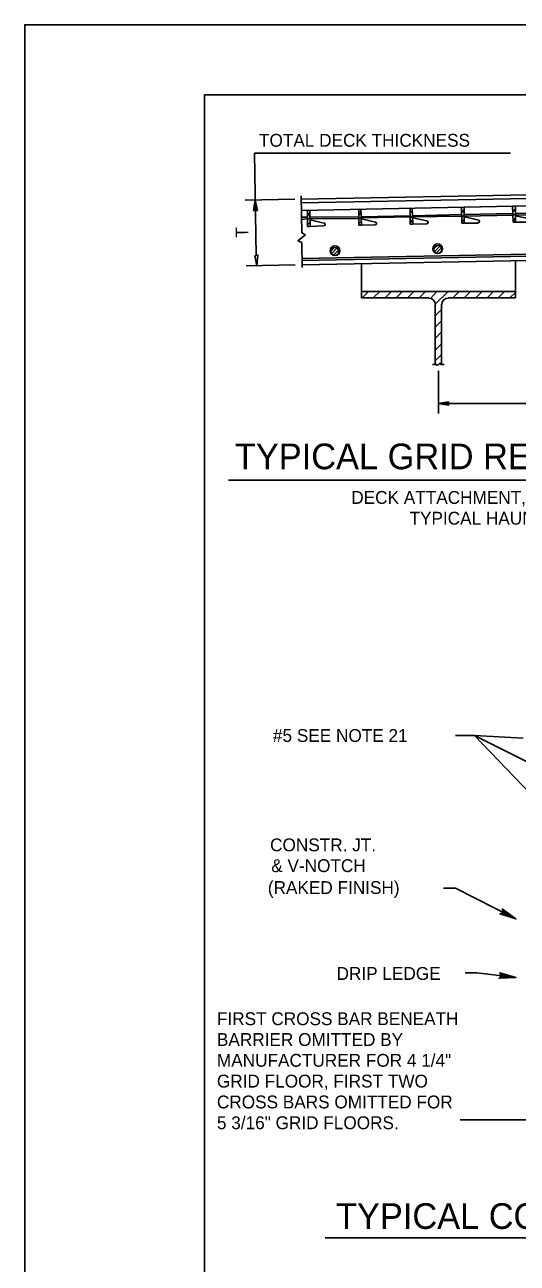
# Model space of a CAD drawing. Extents: x -24512 to -22484, y 4569 to 6351.
# Drawn here: x -24179.8 to -24064.8, y 6061.6 to 6351 of the extents above; entities that cross this region are included whole.
import ezdxf

# ---------------------------------------------------------------- set-up
doc = ezdxf.new("R2010")
doc.units = 0
for name, color, linetype in [('10', 7, 'Continuous'), ('11', 7, 'Continuous'), ('2', 7, 'Continuous'), ('4', 7, 'Continuous'), ('5', 7, 'Continuous'), ('6', 7, 'Continuous'), ('PLT-BNDY', 7, 'Continuous')]:
    doc.layers.add(name, color=color, linetype=linetype)

# ---------------------------------------------------------------- blocks, each defined once
blk = doc.blocks.new('JUQ006')
at = {"layer": '4'}
for p, q in [((10.418625, 11.48775), (10.630375, 11.699625)), ((10.457, 11.312375), (10.805875, 11.66125)), ((10.574625, 11.21625), (10.902, 11.5435)), ((10.82875, 11.256375), (10.86175, 11.2895))]:
    blk.add_line(p, q, dxfattribs=at)
blk = doc.blocks.new('JUQ005')
at = {"layer": '4'}
for p, q in [((12.764875, 6.492125), (12.825, 6.552375)), ((12.764875, 6.207), (12.916, 6.35825)), ((12.764875, 5.921875), (12.916, 6.073125)), ((12.764875, 5.63675), (12.916, 5.788))]:
    blk.add_line(p, q, dxfattribs=at)

msp = doc.modelspace()

# ---------------------------------------------------------------- linework, layer by layer
at = {"layer": '10'}
for p, q in [((-24066.39, 6321.05), (-24126.15, 6321.05)), ((-24125.71, 6297.2), (-24126.15, 6321.05)), ((-24116.73, 6310.29), (-24128.33, 6310.04)), ((-24116.6, 6294.95), (-24128.08, 6294.7)), ((-24083.19, 6270.14), (-24083.19, 6260.17)), ((-24083.19, 6262.53), (-23939.17, 6262.53)), ((-24074.73, 6184.92), (-24079.19, 6184.92)), ((-24062.64, 6178.84), (-24074.73, 6184.92)), ((-24063.38, 6184.3), (-24074.73, 6184.92)), ((-24061.72, 6171.26), (-24074.73, 6184.92)), ((-24079.24, 6149.28), (-24081.98, 6149.28)), ((-24065.08, 6142.05), (-24079.24, 6149.28)), ((-24074.23, 6129.43), (-24076.97, 6129.43)), ((-24065.08, 6128.37), (-24074.23, 6129.43)), ((-24048.21, 6095.14), (-24078.1, 6095.14))]:
    msp.add_line(p, q, dxfattribs=at)
for points in [[(-24126.33, 6307.67), (-24125.46, 6307.67), (-24125.96, 6310.04)], [(-24126.08, 6297.07), (-24125.33, 6297.2), (-24125.58, 6294.7)], [(-24080.82, 6262.91), (-24080.82, 6262.16), (-24083.19, 6262.53)]]:
    msp.add_lwpolyline(points, close=True, dxfattribs=at)
for points in [[(-24068.16, 6144.14), (-24068.16, 6143.84), (-24065.08, 6142.05), (-24068.16, 6144.14), (-24068.26, 6144.37), (-24065.08, 6142.05), (-24068.33, 6143.51), (-24068.56, 6143.33), (-24065.08, 6142.05), (-24068.82, 6143.26), (-24068.56, 6143.33)], [(-24068.7, 6129.26), (-24068.59, 6128.97), (-24065.08, 6128.37), (-24068.7, 6129.26), (-24068.87, 6129.44), (-24065.08, 6128.37), (-24068.63, 6128.6), (-24068.79, 6128.36), (-24065.08, 6128.37), (-24069.01, 6128.2), (-24068.79, 6128.36)]]:
    msp.add_lwpolyline(points, dxfattribs=at)
at = {"layer": '11'}
for p, q in [((-23876.11, 6244.57), (-24132.21, 6244.57)), ((-23923.43, 6067.54), (-24109.65, 6067.54))]:
    msp.add_line(p, q, dxfattribs=at)
at = {"layer": '2'}
for p, q in [((-24137.79, 5772.04), (-24137.79, 6334.63)), ((-24137.79, 6334.63), (-23353.75, 6334.63))]:
    msp.add_line(p, q, dxfattribs=at)
at = {"layer": '5'}
for p, q in [((-24115.23, 6310.29), (-23904.64, 6314.4)), ((-24115.23, 6309.42), (-23904.64, 6313.41)), ((-24115.23, 6307.67), (-23904.64, 6311.79)), ((-24115.23, 6311.04), (-24115.11, 6302.43)), ((-24113.74, 6307.67), (-24113.74, 6303.93)), ((-24113.24, 6307.67), (-24113.11, 6303.93)), ((-24101.77, 6307.92), (-24101.77, 6304.18)), ((-24101.27, 6307.92), (-24101.14, 6304.18)), ((-24089.8, 6308.17), (-24089.8, 6304.43)), ((-24089.3, 6308.17), (-24089.17, 6304.43)), ((-24077.83, 6308.42), (-24077.7, 6304.68)), ((-24077.2, 6308.42), (-24077.2, 6304.68)), ((-24065.86, 6308.67), (-24065.73, 6304.93)), ((-24065.23, 6308.67), (-24065.23, 6304.93)), ((-24115.23, 6306.05), (-24113.74, 6306.05)), ((-24115.23, 6305.55), (-24113.74, 6305.68)), ((-24113.24, 6306.05), (-24101.77, 6306.18)), ((-24113.24, 6305.68), (-24101.77, 6305.8)), ((-24113.24, 6305.43), (-24109.87, 6304.68)), ((-24101.14, 6306.18), (-24089.8, 6306.42)), ((-24101.14, 6305.93), (-24089.8, 6306.18)), ((-24101.14, 6305.68), (-24097.9, 6304.93)), ((-24089.8, 6304.43), (-24089.17, 6304.43)), ((-24089.17, 6306.42), (-24077.83, 6306.67)), ((-24089.17, 6306.18), (-24077.83, 6306.3)), ((-24089.17, 6305.93), (-24085.93, 6305.18)), ((-24089.17, 6304.43), (-24085.93, 6304.55)), ((-24077.7, 6304.68), (-24077.2, 6304.68)), ((-24077.2, 6306.67), (-24065.86, 6306.92)), ((-24077.2, 6306.3), (-24065.73, 6306.55)), ((-24077.2, 6306.18), (-24073.96, 6305.43)), ((-24077.2, 6304.68), (-24073.96, 6304.68)), ((-24065.73, 6304.93), (-24065.23, 6304.93)), ((-24065.23, 6306.92), (-24053.76, 6307.17)), ((-24065.23, 6306.55), (-24053.76, 6306.8)), ((-24065.23, 6306.42), (-24061.87, 6305.68)), ((-24065.23, 6304.93), (-24061.99, 6304.93)), ((-24115.98, 6300.56), (-24114.24, 6301.94)), ((-24115.11, 6302.43), (-24114.24, 6301.94)), ((-24113.74, 6303.93), (-24113.11, 6303.93)), ((-24113.11, 6303.93), (-24110, 6304.06)), ((-24101.77, 6304.18), (-24101.14, 6304.18)), ((-24101.14, 6304.18), (-24097.9, 6304.31)), ((-24115.98, 6300.56), (-24115.11, 6300.19)), ((-24115.11, 6296.45), (-23904.51, 6300.44)), ((-24115.11, 6300.19), (-24114.98, 6294.33)), ((-24115.11, 6295.95), (-23904.51, 6299.94)), ((-24114.98, 6294.95), (-23904.51, 6298.94)), ((-24065.23, 6288.72), (-24065.23, 6295.95)), ((-24101.14, 6288.72), (-24101.14, 6295.2)), ((-24101.14, 6288.72), (-24065.23, 6288.72)), ((-24101.14, 6288.72), (-24101.14, 6287.22)), ((-24101.14, 6287.22), (-24085.43, 6287.22)), ((-24080.94, 6287.22), (-24065.23, 6287.22)), ((-24065.23, 6288.72), (-24065.23, 6287.22)), ((-24083.94, 6285.73), (-24083.94, 6271.64)), ((-24082.44, 6285.73), (-24082.44, 6271.64)), ((-24084.56, 6271.64), (-24083.56, 6271.64)), ((-24083.56, 6271.64), (-24083.44, 6271.39)), ((-24083.44, 6271.39), (-24082.81, 6272.01)), ((-24082.81, 6272.01), (-24082.69, 6271.64)), ((-24082.69, 6271.64), (-24081.82, 6271.64)), ((-24080.82, 6262.53), (-24080.82, 6262.53))]:
    msp.add_line(p, q, dxfattribs=at)
for centre, radius in [((-24107.35, 6298.23), 1.13), ((-24107.35, 6298.04), 0.938), ((-24083.35, 6298.69), 1.13), ((-24083.35, 6298.5), 0.938)]:
    msp.add_circle(centre, radius, dxfattribs=at)
for centre, radius, start, end in [((-24109.99, 6304.42), 0.375, 271.0964, 77.9991), ((-24097.99, 6304.64), 0.375, 271.0964, 77.9991), ((-24085.99, 6304.87), 0.375, 271.0964, 77.9991), ((-24073.99, 6305.1), 0.375, 271.0964, 77.9991), ((-24085.41, 6285.65), 1.5, 0, 90), ((-24080.91, 6285.65), 1.5, 90, 180)]:
    msp.add_arc(centre, radius, start, end, dxfattribs=at)
at = {"layer": '6'}
for p, q in [((-24101.02, 6287.22), (-24099.52, 6288.72)), ((-24098.4, 6287.22), (-24096.9, 6288.72)), ((-24095.66, 6287.22), (-24094.16, 6288.72)), ((-24093.04, 6287.22), (-24091.54, 6288.72)), ((-24090.42, 6287.22), (-24088.92, 6288.72)), ((-24087.68, 6287.22), (-24086.18, 6288.72)), ((-24085.06, 6287.1), (-24083.56, 6288.72)), ((-24083.94, 6285.73), (-24080.94, 6288.72)), ((-24079.82, 6287.22), (-24078.33, 6288.72)), ((-24077.2, 6287.22), (-24075.71, 6288.72)), ((-24074.46, 6287.22), (-24072.96, 6288.72)), ((-24071.84, 6287.22), (-24070.35, 6288.72)), ((-24069.22, 6287.22), (-24067.73, 6288.72)), ((-24066.48, 6287.22), (-24065.23, 6288.47)), ((-24083.94, 6282.98), (-24082.44, 6284.48)), ((-24083.94, 6280.37), (-24082.44, 6281.86)), ((-24083.94, 6277.75), (-24082.44, 6279.24)), ((-24083.94, 6275), (-24082.44, 6276.5)), ((-24083.94, 6272.51), (-24082.44, 6274.01))]:
    msp.add_line(p, q, dxfattribs=at)
at = {"layer": 'PLT-BNDY'}
msp.add_lwpolyline([(-23338.75, 5757.04), (-24179.75, 5757.04), (-24179.75, 6351.04), (-23338.75, 6351.04)], close=True, dxfattribs=at)

# ---------------------------------------------------------------- block references
at = {"layer": '4', "xscale": 3.720483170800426, "yscale": 3.720483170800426, "rotation": 1.0964384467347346}
for name, p in [('JUQ005', (-24160.74, 6282.48)), ('JUQ005', (-24148.77, 6282.73)), ('JUQ005', (-24136.8, 6282.98)), ('JUQ005', (-24124.83, 6283.11)), ('JUQ005', (-24112.86, 6283.36)), ('JUQ006', (-24146.28, 6254.68)), ('JUQ006', (-24122.22, 6255.18))]:
    msp.add_blockref(name, p, dxfattribs=at)

# ---------------------------------------------------------------- texts
at = {"layer": '10'}
for s, p in [('TOTAL DECK THICKNESS', (-24125.08, 6322.54)), ('DECK ATTACHMENT, PANEL SPLICE AND HAUNCH DETAILS SHOWN ON SHEET 2.', (-24103.53, 6239.07)), ('TYPICAL HAUNCH FOR GIRDERS SHOWN FOR ILLUSTRATION ONLY.', (-24089.94, 6234.21)), ('#5 SEE NOTE 21', (-24121.82, 6183.43)), ('CONSTR. JT.', (-24122.49, 6157.87)), ('& V-NOTCH', (-24122.22, 6153.01)), ('(RAKED FINISH)', (-24123.01, 6147.89)), ('DRIP LEDGE', (-24106.97, 6127.81)), ('FIRST CROSS BAR BENEATH ', (-24134.9, 6117.23)), ('BARRIER OMITTED BY ', (-24134.9, 6112.37)), ('MANUFACTURER FOR 4 1/4"', (-24134.9, 6107.51)), ('GRID FLOOR, FIRST TWO ', (-24134.9, 6102.65)), ('CROSS BARS OMITTED FOR ', (-24134.9, 6097.78)), ('5 3/16" GRID FLOORS.', (-24134.9, 6092.92))]:
    msp.add_text(s, height=3, dxfattribs=at).set_placement(p)
msp.add_text('T', height=3, rotation=91.0964, dxfattribs=at).set_placement((-24127.52, 6301.31))
at = {"layer": '11'}
for s, p in [('TYPICAL GRID REINFORCED CONCRETE DECK PANEL', (-24130.72, 6247.16)), ('TYPICAL CONCRETE BARRIER DETAIL', (-24107.11, 6069.61))]:
    msp.add_text(s, height=6.0008, dxfattribs=at).set_placement(p)

doc.saveas('drawing.dxf')
